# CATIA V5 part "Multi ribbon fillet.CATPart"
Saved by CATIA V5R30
Part number: Part1
Bounding box of the stored display mesh (mm): x -200 to 0, y -56.059 to 216.476, z -47.66 to 28.91
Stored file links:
  D:\PROJECTS\CATIA V56R 2020\Resources\Parts File\c17_catia_v6_6r2020_prt\Multi ribbon fillet.CATPart
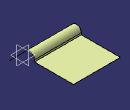
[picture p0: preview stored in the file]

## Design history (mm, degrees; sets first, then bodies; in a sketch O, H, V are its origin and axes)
Set1
  Sketch1 on yz-plane, origin (0, 0, 0), H (0, 1, 0), V (0, 0, 1)
    point P1 (0, 30)
    line L1 (0, 30) -> (50, 30)
    line L2 (50, 30) -> (50, 0)
    point P3 (50, 0)
    line L3 (50, 0) -> (216.476, 0)
    length L1 = 50
    length L2 = 30
    coincidence: P1 V, P3 H
    horizontal: L1 H, L3 H
    vertical: L2 V
  Extrude1: Element1 Sketch1, Lim1 200, Lim2 0
  Sketch2 on yz-plane, origin (0, 0, 0), H (0, 1, 0), V (0, 0, 1)
    line L1 (35.5115, 44.1839) -> (-56.0594, -47.6596)
  Extrude2: Element1 Sketch2, Lim1 200, Lim2 0
  Fillet1: type BiTangent, Element1 Extrude2, Element2 Extrude1, Radius 21, FacesToKeep face of Extrude1 from Sketch1.L2
Body1 (main body)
